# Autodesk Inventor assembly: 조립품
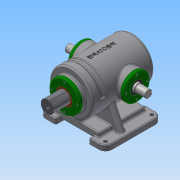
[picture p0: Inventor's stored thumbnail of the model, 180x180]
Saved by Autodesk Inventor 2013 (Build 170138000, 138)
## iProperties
Created: 2018-06
Part Number: 조립품
Document SubType Name: Assembly
Designer: Administrator
Author: Administrator
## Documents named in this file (13)
- C:\Users\Administrator\Desktop\380628V1013\조립품.iam
- C:\Users\Administrator\Desktop\380628V1013\본체.ipt
- C:\Users\Administrator\Desktop\380628V1013\가변스프링.ipt
- C:\Users\Administrator\Desktop\380628V1013\베어링 6205.ipt
- 베어링 6205.ipt
- C:\Users\Administrator\Desktop\380628V1013\볼트 M4.ipt
- C:\Users\Administrator\Desktop\380628V1013\부시.ipt
- C:\Users\Administrator\Desktop\380628V1013\슬라이드 커버.ipt
- C:\Users\Administrator\Desktop\380628V1013\슬라이드.ipt
- C:\Users\Administrator\Desktop\380628V1013\오일실.ipt
- 오일실.ipt
- C:\Users\Administrator\Desktop\380628V1013\축 커버.ipt
- C:\Users\Administrator\Desktop\380628V1013\편심축.ipt
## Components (1 placed, 1 different names)
1. 가변스프링:1
